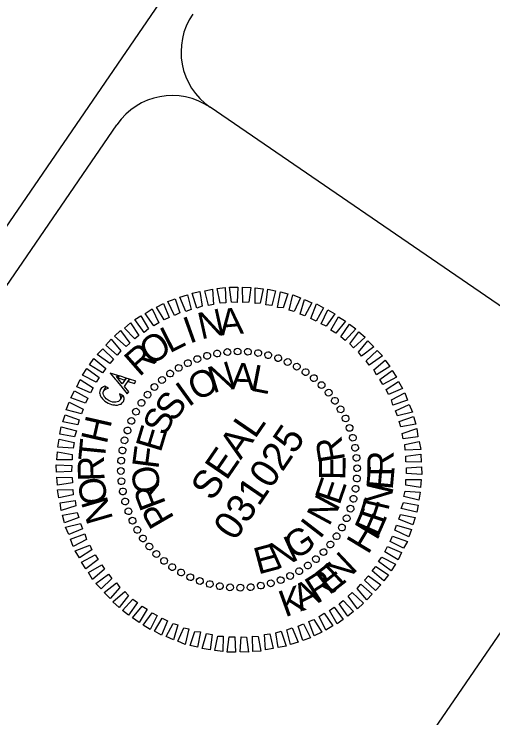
# Model space of a CAD drawing. Extents: x 2312641 to 2338852, y 590461 to 618614.
# Drawn here: x 2334572 to 2335572, y 607939 to 609408 of the extents above; entities that cross this region are included whole.
import ezdxf

# ---------------------------------------------------------------- set-up
doc = ezdxf.new("R2010")
doc.units = 0
doc.layers.add('Default', color=7, linetype='Continuous')
doc.layers.add('Exist Property Iron Pin Cogo Number', color=7, linetype='Continuous')

msp = doc.modelspace()

# ---------------------------------------------------------------- linework, layer by layer
at = {"layer": 'Default'}
for p, q in [((2335018.2, 608703.1), (2335018.2, 608703.1)), ((2335018.2, 608703.1), (2335018.2, 608703.1)), ((2335038.9, 608704.2), (2335038.9, 608704.2)), ((2335038.9, 608704.2), (2335038.9, 608704.2)), ((2335060.7, 608703.3), (2335060.7, 608703.3)), ((2335060.7, 608703.3), (2335060.7, 608703.3)), ((2334954.6, 608687.9), (2334954.6, 608687.9)), ((2334954.6, 608687.9), (2334954.6, 608687.9)), ((2334975.4, 608695.4), (2334975.4, 608695.4)), ((2334975.4, 608695.4), (2334975.4, 608695.4)), ((2334996.1, 608700), (2334996.1, 608700)), ((2334996.1, 608700), (2334996.1, 608700)), ((2335081.9, 608700.6), (2335081.9, 608700.6)), ((2335081.9, 608700.6), (2335081.9, 608700.6)), ((2335102.6, 608696.4), (2335102.6, 608696.4)), ((2335102.6, 608696.4), (2335102.6, 608696.4)), ((2335123.4, 608690.4), (2335123.4, 608690.4)), ((2335123.4, 608690.4), (2335123.4, 608690.4)), ((2334934.9, 608680.2), (2334934.9, 608680.2)), ((2334934.9, 608680.2), (2334934.9, 608680.2)), ((2335143.6, 608681.8), (2335143.6, 608681.8)), ((2335143.6, 608681.8), (2335143.6, 608681.8)), ((2334915.8, 608669.2), (2334915.8, 608669.2)), ((2334915.8, 608669.2), (2334915.8, 608669.2)), ((2335162.9, 608672.6), (2335162.9, 608672.6)), ((2335162.9, 608672.6), (2335162.9, 608672.6)), ((2335181.2, 608661.1), (2335181.2, 608661.1)), ((2335181.2, 608661.1), (2335181.2, 608661.1)), ((2334880.8, 608644.6), (2334880.8, 608644.6)), ((2334880.8, 608644.6), (2334880.8, 608644.6)), ((2334897.9, 608658.1), (2334897.9, 608658.1)), ((2334897.9, 608658.1), (2334897.9, 608658.1)), ((2335198.5, 608648), (2335198.5, 608648)), ((2335198.5, 608648), (2335198.5, 608648)), ((2334865.5, 608629.4), (2334865.5, 608629.4)), ((2334865.5, 608629.4), (2334865.5, 608629.4)), ((2335214.3, 608633.5), (2335214.3, 608633.5)), ((2335214.3, 608633.5), (2335214.3, 608633.5)), ((2335229.1, 608618.5), (2335229.1, 608618.5)), ((2335229.1, 608618.5), (2335229.1, 608618.5)), ((2334851, 608613.6), (2334851, 608613.6)), ((2334851, 608613.6), (2334851, 608613.6)), ((2335242.6, 608601.4), (2335242.6, 608601.4)), ((2335242.6, 608601.4), (2335242.6, 608601.4)), ((2334837.9, 608596.3), (2334837.9, 608596.3)), ((2334837.9, 608596.3), (2334837.9, 608596.3)), ((2334826.4, 608578), (2334826.4, 608578)), ((2334826.4, 608578), (2334826.4, 608578)), ((2335254.1, 608583.2), (2335254.1, 608583.2)), ((2335254.1, 608583.2), (2335254.1, 608583.2)), ((2334817.2, 608558.7), (2334817.2, 608558.7)), ((2334817.2, 608558.7), (2334817.2, 608558.7)), ((2335264.7, 608564.4), (2335264.7, 608564.4)), ((2335264.7, 608564.4), (2335264.7, 608564.4)), ((2335272.8, 608544.4), (2335272.8, 608544.4)), ((2335272.8, 608544.4), (2335272.8, 608544.4)), ((2334808.9, 608538.9), (2334808.9, 608538.9)), ((2334808.9, 608538.9), (2334808.9, 608538.9)), ((2334802.5, 608518.4), (2334802.5, 608518.4)), ((2334802.5, 608518.4), (2334802.5, 608518.4)), ((2335280.3, 608523.6), (2335280.3, 608523.6)), ((2335280.3, 608523.6), (2335280.3, 608523.6)), ((2334798, 608497.2), (2334798, 608497.2)), ((2334798, 608497.2), (2334798, 608497.2)), ((2335284.5, 608503.2), (2335284.5, 608503.2)), ((2335284.5, 608503.2), (2335284.5, 608503.2)), ((2334795.9, 608476.2), (2334795.9, 608476.2)), ((2334795.9, 608476.2), (2334795.9, 608476.2)), ((2335287.6, 608481.1), (2335287.6, 608481.1)), ((2335287.6, 608481.1), (2335287.6, 608481.1)), ((2334794.8, 608454), (2334794.8, 608454)), ((2334794.8, 608454), (2334794.8, 608454)), ((2335041.9, 608457.4), (2335041.9, 608457.4)), ((2335041.9, 608457.4), (2335041.9, 608457.4)), ((2335288.7, 608460.4), (2335288.7, 608460.4)), ((2335288.7, 608460.4), (2335288.7, 608460.4)), ((2335287.9, 608438.6), (2335287.9, 608438.6)), ((2335287.9, 608438.6), (2335287.9, 608438.6)), ((2334795.9, 608433.3), (2334795.9, 608433.3)), ((2334795.9, 608433.3), (2334795.9, 608433.3)), ((2334799.3, 608411.6), (2334799.3, 608411.6)), ((2334799.3, 608411.6), (2334799.3, 608411.6)), ((2335285.5, 608417.1), (2335285.5, 608417.1)), ((2335285.5, 608417.1), (2335285.5, 608417.1)), ((2335281, 608396), (2335281, 608396)), ((2335281, 608396), (2335281, 608396)), ((2334803.9, 608390.9), (2334803.9, 608390.9)), ((2334803.9, 608390.9), (2334803.9, 608390.9)), ((2334810.7, 608369.9), (2334810.7, 608369.9)), ((2334810.7, 608369.9), (2334810.7, 608369.9)), ((2335274.9, 608375.9), (2335274.9, 608375.9)), ((2335274.9, 608375.9), (2335274.9, 608375.9)), ((2334818.8, 608350), (2334818.8, 608350)), ((2334818.8, 608350), (2334818.8, 608350)), ((2335266.3, 608355.7), (2335266.3, 608355.7)), ((2335266.3, 608355.7), (2335266.3, 608355.7)), ((2335257.1, 608336.4), (2335257.1, 608336.4)), ((2335257.1, 608336.4), (2335257.1, 608336.4)), ((2334829.4, 608331.2), (2334829.4, 608331.2)), ((2334829.4, 608331.2), (2334829.4, 608331.2)), ((2334841, 608313), (2334841, 608313)), ((2334841, 608313), (2334841, 608313)), ((2335245.6, 608318.1), (2335245.6, 608318.1)), ((2335245.6, 608318.1), (2335245.6, 608318.1)), ((2334854.4, 608295.9), (2334854.4, 608295.9)), ((2334854.4, 608295.9), (2334854.4, 608295.9)), ((2335232.5, 608300.8), (2335232.5, 608300.8)), ((2335232.5, 608300.8), (2335232.5, 608300.8)), ((2334869.3, 608280.8), (2334869.3, 608280.8)), ((2334869.3, 608280.8), (2334869.3, 608280.8)), ((2335218, 608285), (2335218, 608285)), ((2335218, 608285), (2335218, 608285)), ((2334885.7, 608266.5), (2334885.7, 608266.5)), ((2334885.7, 608266.5), (2334885.7, 608266.5)), ((2335203, 608270.2), (2335203, 608270.2)), ((2335203, 608270.2), (2335203, 608270.2)), ((2334903, 608253.4), (2334903, 608253.4)), ((2334903, 608253.4), (2334903, 608253.4)), ((2335186, 608256), (2335186, 608256)), ((2335186, 608256), (2335186, 608256)), ((2334921.3, 608241.9), (2334921.3, 608241.9)), ((2334921.3, 608241.9), (2334921.3, 608241.9)), ((2334940.2, 608233), (2334940.2, 608233)), ((2334940.2, 608233), (2334940.2, 608233)), ((2335148.9, 608234.6), (2335148.9, 608234.6)), ((2335148.9, 608234.6), (2335148.9, 608234.6)), ((2335168.1, 608244.9), (2335168.1, 608244.9)), ((2335168.1, 608244.9), (2335168.1, 608244.9)), ((2334960.4, 608224.4), (2334960.4, 608224.4)), ((2334960.4, 608224.4), (2334960.4, 608224.4)), ((2334980.9, 608218), (2334980.9, 608218)), ((2334980.9, 608218), (2334980.9, 608218)), ((2335108.1, 608219), (2335108.1, 608219)), ((2335108.1, 608219), (2335108.1, 608219)), ((2335128.9, 608226.5), (2335128.9, 608226.5)), ((2335128.9, 608226.5), (2335128.9, 608226.5)), ((2335002, 608213.5), (2335002, 608213.5)), ((2335002, 608213.5), (2335002, 608213.5)), ((2335023.1, 608211.4), (2335023.1, 608211.4)), ((2335023.1, 608211.4), (2335023.1, 608211.4)), ((2335044.9, 608210.6), (2335044.9, 608210.6)), ((2335044.9, 608210.6), (2335044.9, 608210.6)), ((2335066, 608211.4), (2335066, 608211.4)), ((2335066, 608211.4), (2335066, 608211.4)), ((2335087.7, 608214.8), (2335087.7, 608214.8)), ((2335087.7, 608214.8), (2335087.7, 608214.8))]:
    msp.add_line(p, q, dxfattribs=at)
for points in [[(2335002.2, 608804.9), (2334996.5, 608835.6), (2335012.9, 608837.2), (2335014.2, 608805.2)], [(2335026.3, 608806.7), (2335022.3, 608838.1), (2335039.3, 608838.1), (2335037.7, 608806.2)], [(2335050.1, 608806.3), (2335048.9, 608838.3), (2335066.7, 608837.7), (2335062.1, 608806.6)], [(2335075.4, 608804.4), (2335075.7, 608837.1), (2335092.3, 608834.5), (2335086.3, 608804.8)], [(2334930.8, 608787.7), (2334918.3, 608817), (2334934.3, 608822.5), (2334941.7, 608791.7)], [(2334953.9, 608794.2), (2334944, 608825.5), (2334959.9, 608829.2), (2334965.1, 608798.6)], [(2334978.1, 608799.6), (2334970.6, 608830.3), (2334986.6, 608834), (2334988.5, 608802.1)], [(2335098, 608801.2), (2335102.3, 608833.7), (2335118.3, 608830.3), (2335110, 608799.8)], [(2335122.2, 608795.9), (2335128.3, 608828.4), (2335144, 608824.5), (2335133.8, 608794.8)], [(2335146.5, 608789.9), (2335154.4, 608822.4), (2335169.9, 608815.7), (2335157, 608787.1)], [(2334907.4, 608778.9), (2334893.2, 608808.3), (2334908.7, 608814), (2334918, 608784.3)], [(2335169.4, 608781.9), (2335178.4, 608812.5), (2335194, 608805.8), (2335179.4, 608778.3)], [(2334864.3, 608757.3), (2334846.2, 608783.3), (2334860.5, 608792.7), (2334874.4, 608763.6)], [(2334885.5, 608769.8), (2334869.7, 608796.7), (2334884.5, 608804), (2334895.8, 608774.8)], [(2335191.6, 608772.6), (2335203.4, 608803.1), (2335218.2, 608795.1), (2335203, 608767.5)], [(2335213.1, 608761.4), (2335227.2, 608791), (2335241.7, 608782.6), (2335223.4, 608756.5)], [(2334843.7, 608743.8), (2334824.3, 608770.7), (2334837.2, 608778.6), (2334852.8, 608751.3)], [(2335233.5, 608748.6), (2335249.8, 608776.1), (2335263.8, 608766.9), (2335243.6, 608742.5)], [(2334824.4, 608730.6), (2334803.1, 608752.8), (2334815.4, 608763.5), (2334832.9, 608737.3)], [(2335254.4, 608734.8), (2335272.4, 608761.2), (2335285.4, 608751.5), (2335263.5, 608727.1)], [(2334806.1, 608714.4), (2334782.1, 608736), (2334794.6, 608747.8), (2334814.2, 608721.4)], [(2335272.8, 608719.8), (2335292.2, 608744.7), (2335305, 608733.9), (2335280.9, 608711.5)], [(2334787.5, 608696), (2334763.9, 608717.4), (2334774.9, 608729.6), (2334795.2, 608705)], [(2335290.9, 608702.6), (2335310.9, 608725.9), (2335323, 608713.8), (2335297.6, 608694)], [(2334771.9, 608678.6), (2334745.6, 608697.6), (2334757.7, 608709.7), (2334779.6, 608687.6)], [(2335307.1, 608684.3), (2335329.9, 608706.3), (2335341.1, 608694.8), (2335313.8, 608675.7)], [(2334756.8, 608659.1), (2334729.8, 608676.3), (2334739.1, 608689.6), (2334763.7, 608668.7)], [(2335323, 608665.5), (2335347.2, 608686.1), (2335356.4, 608672.4), (2335328.7, 608655.4)], [(2334743.4, 608639.7), (2334715.1, 608654.8), (2334724.4, 608668.1), (2334750.3, 608649.3)], [(2334799.8, 608626.2), (2334808.6, 608615.3), (2334811.8, 608620), (2334802.9, 608630.7), (2334813.4, 608646.1), (2334806.4, 608648.3), (2334798.2, 608636.4), (2334790.4, 608645.8), (2334790.4, 608645.8), (2334788.3, 608648.1), (2334788.2, 608648.1), (2334786.2, 608650.1), (2334788.8, 608654), (2334773.1, 608659), (2334783.5, 608646.2), (2334785.4, 608643.9), (2334785.4, 608643.8), (2334787.4, 608641.5), (2334787.4, 608641.4), (2334795.2, 608631.9)], [(2335335.7, 608645.4), (2335361.6, 608664.3), (2335370.6, 608650.1), (2335341.8, 608635)], [(2334731.9, 608617.8), (2334703.1, 608630.3), (2334710, 608645.2), (2334737.6, 608628.2)], [(2334786.2, 608650.1), (2334788.8, 608649), (2334791.6, 608653.1), (2334788.8, 608654)], [(2334791.8, 608647.9), (2334803.4, 608644), (2334806.4, 608648.3), (2334794.7, 608652.1), (2334794.6, 608652.1), (2334791.7, 608653), (2334791.6, 608653.1), (2334788.8, 608649), (2334788.9, 608649), (2334791.7, 608647.9)], [(2334810.3, 608641.6), (2334823.5, 608637.1), (2334826.7, 608641.8), (2334813.4, 608646.1)], [(2334798.3, 608596.8), (2334800.7, 608599.5), (2334802.2, 608604.4), (2334802, 608606.2), (2334801.8, 608608.7), (2334801.1, 608610.9), (2334798.6, 608612.2), (2334798.5, 608612.2), (2334793.6, 608602.7), (2334791, 608599.9), (2334790.5, 608599.5), (2334787.3, 608598.5), (2334785.1, 608597.8), (2334781.2, 608598.1), (2334778, 608598.4), (2334771, 608601.1), (2334771, 608601.1), (2334764.6, 608605.4), (2334762.5, 608607.8), (2334760.5, 608610.1), (2334760.1, 608610.5), (2334759, 608613.7), (2334758.2, 608616), (2334758.5, 608617.5), (2334759.1, 608620.8), (2334764, 608630.2), (2334763.9, 608630.2), (2334761.8, 608631.3), (2334758.9, 608630.3), (2334756.8, 608629), (2334755.1, 608628), (2334751.9, 608623.7), (2334751.4, 608620.7), (2334750.8, 608617.4), (2334751.4, 608615.6), (2334752.3, 608612.8), (2334753.4, 608609.5), (2334753.4, 608609.5), (2334754, 608608.8), (2334754.3, 608608.4), (2334755.6, 608606.9), (2334757.2, 608604.9), (2334757.6, 608604.5), (2334759.6, 608602.1), (2334762.1, 608600.4), (2334768.5, 608596.1), (2334768.5, 608596.1), (2334775.5, 608593.5), (2334778.4, 608592.5), (2334782.3, 608592.2), (2334784.1, 608592), (2334786.6, 608591.8), (2334786.8, 608591.8), (2334788, 608591.7), (2334788.1, 608591.7), (2334791.9, 608593), (2334794.1, 608593.7), (2334795.9, 608594.2)], [(2334768.5, 608627), (2334769.3, 608627.2), (2334768.8, 608627.5), (2334766.7, 608628.6), (2334765.1, 608629.5), (2334765.1, 608629.5), (2334764.8, 608629.7), (2334764, 608630.2), (2334759.1, 608620.8), (2334761.9, 608624.2), (2334762.6, 608624.6), (2334765.4, 608626.2)], [(2335349.2, 608624.8), (2335374.6, 608641), (2335383.3, 608626.5), (2335353.5, 608614.3)], [(2334721.2, 608596), (2334690.8, 608607.2), (2334698.5, 608621.5), (2334726.4, 608606.7)], [(2334794.8, 608607.3), (2334793.6, 608602.7), (2334798.5, 608612.2), (2334797.5, 608612.7), (2334797.3, 608612.8), (2334795.2, 608613.9), (2334793.8, 608614.6), (2334792.7, 608615.2), (2334792.7, 608615.2), (2334793.3, 608613.7), (2334794.1, 608611.6), (2334794.7, 608607.6)], [(2335360.4, 608603.3), (2335388.2, 608617.9), (2335393.7, 608602), (2335363.2, 608591.5)], [(2334713.4, 608573.5), (2334681.4, 608582.2), (2334687.7, 608598), (2334716.3, 608583.3)], [(2335368.7, 608580.2), (2335397.2, 608593.2), (2335403.7, 608577.1), (2335372.7, 608569.3)], [(2334705.3, 608550.5), (2334674.2, 608556.9), (2334679.3, 608571.8), (2334708.1, 608561.1)], [(2335376.2, 608557.6), (2335406.2, 608568.4), (2335410.7, 608551.9), (2335379.5, 608546.6)], [(2334698.4, 608525.7), (2334667.8, 608531.1), (2334671, 608546.7), (2334702.9, 608538)], [(2335382.3, 608532.9), (2335412.9, 608542.8), (2335415.4, 608525.9), (2335384.3, 608521.7)], [(2334695.4, 608502.3), (2334663.8, 608504.3), (2334666.4, 608520.8), (2334698.1, 608513.6)], [(2335387.8, 608510), (2335417.7, 608516.1), (2335421.3, 608499.1), (2335388.8, 608498.1)], [(2334693.4, 608477.8), (2334661.5, 608477.6), (2334663.3, 608494.7), (2334693.6, 608488.8)], [(2335389.7, 608485.1), (2335421, 608489.8), (2335422.1, 608472.6), (2335390.3, 608473.5)], [(2334692, 608453.4), (2334661.1, 608451.9), (2334660.4, 608467.1), (2334693.1, 608465.7)], [(2335391.5, 608461), (2335422.7, 608462.8), (2335423.5, 608447), (2335391.2, 608448.9)], [(2334694.1, 608429.7), (2334662.7, 608425), (2334661.8, 608441.5), (2334693.9, 608441)], [(2335390.1, 608436.6), (2335422, 608436.8), (2335420.5, 608420.1), (2335390.1, 608424.9)], [(2334696, 608404.9), (2334666, 608398.7), (2334662.7, 608415), (2334695.1, 608416)], [(2335388.4, 608412.4), (2335420, 608410.5), (2335417.1, 608393.5), (2335386.1, 608401)], [(2334701.5, 608381.8), (2334670.8, 608372), (2334668.6, 608388.2), (2334699.6, 608392.5)], [(2335385.1, 608388.7), (2335415.7, 608383.3), (2335412.8, 608368.2), (2335380.5, 608376.4)], [(2334707.6, 608357.2), (2334677.5, 608346.4), (2334673.2, 608362.2), (2334704.4, 608367.5)], [(2335378.6, 608363.6), (2335409.3, 608357.5), (2335404.6, 608342.3), (2335375.6, 608353.7)], [(2334715.2, 608333.9), (2334686.5, 608321.6), (2334679.8, 608337.3), (2334710.8, 608345.1)], [(2335370.8, 608341), (2335402.1, 608332.2), (2335396.1, 608316.8), (2335367.2, 608331.1)], [(2334723.2, 608311.1), (2334696, 608296.6), (2334689.9, 608312.3), (2334720.4, 608322.9)], [(2335362.3, 608318.3), (2335393.4, 608307.4), (2335385.3, 608293.3), (2335357.5, 608307.4)], [(2334734.6, 608290), (2334708.9, 608273.3), (2334700.2, 608287.9), (2334730.5, 608299.8)], [(2335351.6, 608296.6), (2335381.1, 608284.2), (2335374, 608268.9), (2335346.3, 608285.9)], [(2334748.1, 608269.3), (2334721.9, 608250.1), (2334713.3, 608264), (2334741.8, 608279.4)], [(2335340.1, 608274.7), (2335368.4, 608259.6), (2335359.1, 608246.3), (2335333.2, 608265.1)], [(2334760.8, 608249.3), (2334736.3, 608228.2), (2334727.4, 608242.4), (2334755.3, 608258.8)], [(2335327.2, 608255), (2335354.1, 608237.9), (2335344.4, 608224.8), (2335319.8, 608245.7)], [(2334776.4, 608230.1), (2334754.3, 608208.1), (2334743.1, 608219.7), (2334769.7, 608238.7)], [(2335312, 608235.5), (2335337.9, 608216.7), (2335326.5, 608204.8), (2335303.9, 608226.8)], [(2334792.8, 608211.1), (2334772.6, 608188.5), (2334760.5, 608200.6), (2334786.1, 608220.8)], [(2335296, 608218.4), (2335319.9, 608197.4), (2335308.9, 608185.2), (2335288.7, 608209.1)], [(2334811.1, 608194.3), (2334791.4, 608169.7), (2334778.8, 608180.9), (2334803.3, 608203)], [(2335277.7, 608200.4), (2335301.7, 608178.8), (2335289, 608166.5), (2335270, 608193.1)], [(2334829.8, 608179.7), (2334811.4, 608153.5), (2334798.4, 608163.3), (2334820.4, 608187)], [(2335259.4, 608184.2), (2335280.8, 608161.3), (2335268.7, 608151), (2335250.6, 608177.1)], [(2334850, 608165.8), (2334833.7, 608138.3), (2334819.7, 608147.5), (2334839.9, 608171.9)], [(2335240.3, 608170.3), (2335259.5, 608144.1), (2335246.7, 608135.5), (2335230.8, 608163.1)], [(2334870.8, 608152.7), (2334856.3, 608123.4), (2334842, 608132.2), (2334860.4, 608158.4)], [(2334892.3, 608141.5), (2334880.4, 608111.7), (2334865.6, 608119.7), (2334881.2, 608147)], [(2335198, 608144.6), (2335214.5, 608117.8), (2335199, 608110.4), (2335187.9, 608140)], [(2335219.9, 608157.3), (2335237.4, 608131.1), (2335223.2, 608122.1), (2335209.2, 608150.8)], [(2334914.3, 608132.9), (2334905.1, 608101.9), (2334889.5, 608108.6), (2334904.5, 608135.9)], [(2335176.1, 608135.4), (2335190.7, 608105.8), (2335174.8, 608100.4), (2335165.5, 608130.1)], [(2334937.3, 608124.9), (2334929.2, 608092), (2334914.3, 608098.8), (2334926.5, 608127.3)], [(2334961.3, 608118.5), (2334955.5, 608086.4), (2334939.8, 608090.3), (2334949.7, 608119.6)], [(2334985.5, 608113.2), (2334981.9, 608080.8), (2334965.2, 608084.1), (2334973.8, 608115)], [(2335105.9, 608114.6), (2335113.3, 608083.8), (2335097.2, 608080.8), (2335095.3, 608112.7)], [(2335130, 608119.9), (2335140, 608088.6), (2335123.9, 608085.7), (2335118.7, 608116.2)], [(2335153, 608127.1), (2335165.6, 608097.1), (2335149.5, 608092.3), (2335141.8, 608122.7)], [(2335008.5, 608109.7), (2335007.8, 608077.3), (2334991.3, 608079.9), (2334997.5, 608109.9)], [(2335033.4, 608108.1), (2335034.7, 608076.1), (2335017.2, 608076.4), (2335021.6, 608108.2)], [(2335057.3, 608107.7), (2335061.7, 608076), (2335044.5, 608076.7), (2335046.5, 608108.4)], [(2335081.8, 608109.2), (2335087.4, 608078.5), (2335070.9, 608077.5), (2335069.7, 608109.6)]]:
    msp.add_lwpolyline(points, close=True, dxfattribs=at)
for centre, major_axis in [((2334975.2, 608694.8), (-1.91, 6.82)), ((2334996.2, 608699.7), (-1.31, 6.96)), ((2335017.5, 608702.8), (-0.7, 7.05)), ((2335038.9, 608703.9), (-0.08, 7.08)), ((2335060.4, 608703.3), (0.54, 7.06)), ((2335081.8, 608700.7), (1.15, 6.99)), ((2335102.9, 608696.3), (1.75, 6.86)), ((2334935, 608679.6), (-3.07, 6.38)), ((2334954.8, 608688.1), (-2.5, 6.62)), ((2335123.5, 608690), (2.34, 6.68)), ((2335143.4, 608682), (2.92, 6.45)), ((2334916, 608669.5), (-3.61, 6.09)), ((2335162.6, 608672.3), (3.47, 6.17)), ((2334898, 608657.7), (-4.13, 5.75)), ((2335180.9, 608661), (3.99, 5.85)), ((2334881.1, 608644.4), (-4.61, 5.37)), ((2335198.1, 608648.1), (4.49, 5.48)), ((2334865.4, 608629.7), (-5.06, 4.95)), ((2335214.1, 608633.7), (4.95, 5.06)), ((2334851.1, 608613.7), (-5.48, 4.49)), ((2335228.9, 608618), (5.37, 4.61)), ((2334838.2, 608596.5), (-5.85, 3.99)), ((2335242.1, 608601.1), (5.75, 4.13)), ((2334826.8, 608578.2), (-6.17, 3.47)), ((2335253.9, 608583.1), (6.09, 3.61)), ((2335264.1, 608564.1), (6.38, 3.07)), ((2334817.1, 608559), (-6.45, 2.92)), ((2334809.1, 608539), (-6.68, 2.34)), ((2335272.5, 608544.3), (6.62, 2.5)), ((2334802.9, 608518.4), (-6.86, 1.75)), ((2335279.2, 608523.9), (6.82, 1.91)), ((2334798.4, 608497.4), (-6.99, 1.15)), ((2335284.1, 608503), (6.96, 1.31)), ((2334795.9, 608476), (-7.06, 0.54)), ((2335287.2, 608481.7), (7.05, 0.7)), ((2335288.4, 608460.2), (7.08, 0.08)), ((2334795.2, 608454.5), (-7.08, -0.08)), ((2334796.4, 608433), (-7.05, -0.7)), ((2335287.7, 608438.7), (7.06, -0.54)), ((2335285.1, 608417.3), (6.99, -1.15)), ((2334799.4, 608411.8), (-6.96, -1.31)), ((2334804.3, 608390.8), (-6.82, -1.91)), ((2335280.7, 608396.3), (6.86, -1.75)), ((2335274.5, 608375.7), (6.68, -2.34)), ((2334811, 608370.4), (-6.62, -2.5)), ((2334819.5, 608350.6), (-6.38, -3.07)), ((2335266.5, 608355.7), (6.45, -2.92)), ((2334829.6, 608331.6), (-6.09, -3.61)), ((2335256.7, 608336.5), (6.17, -3.47)), ((2334841.4, 608313.6), (-5.75, -4.13)), ((2335245.4, 608318.2), (5.85, -3.99)), ((2335232.5, 608301), (5.48, -4.49)), ((2334854.7, 608296.7), (-5.37, -4.61)), ((2335218.1, 608285), (5.06, -4.95)), ((2334869.4, 608281), (-4.95, -5.06)), ((2335202.4, 608270.3), (4.61, -5.37)), ((2334885.4, 608266.6), (-4.49, -5.48)), ((2334902.6, 608253.7), (-3.99, -5.85)), ((2335185.5, 608257), (4.13, -5.75)), ((2334920.9, 608242.4), (-3.47, -6.17)), ((2335167.5, 608245.2), (3.61, -6.09)), ((2334940.1, 608232.7), (-2.92, -6.45)), ((2334960.1, 608224.7), (-2.34, -6.68)), ((2335128.8, 608226.6), (2.5, -6.62)), ((2335148.5, 608235.1), (3.07, -6.38)), ((2334980.7, 608218.4), (-1.75, -6.86)), ((2335001.7, 608214), (-1.15, -6.99)), ((2335023.1, 608211.5), (-0.54, -7.06)), ((2335044.6, 608210.8), (0.08, -7.08)), ((2335066.1, 608212), (0.7, -7.05)), ((2335087.4, 608215), (1.31, -6.96)), ((2335108.3, 608219.9), (1.91, -6.82))]:
    msp.add_ellipse(centre, major_axis=major_axis, ratio=0.999708, dxfattribs=at)
at = {"layer": 'Exist Property Iron Pin Cogo Number'}
for p, q in [((2324877.7, 594842), (2336116.1, 611240.6)), ((2336829.3, 607947.5), (2334981.6, 609213.7)), ((2333205.9, 606870.4), (2334787, 609177.4)), ((2334158.7, 606032.4), (2335905.2, 608580.8))]:
    msp.add_line(p, q, dxfattribs=at)
for centre, start, end in [((2335060.8, 609329.2), 145.5761, 235.5761), ((2334902.5, 609098.3), 55.5761, 145.5761)]:
    msp.add_arc(centre, 140, start, end, dxfattribs=at)

# ---------------------------------------------------------------- texts
at = {"layer": 'Default'}
for s, height, rotation, p in [('N', 55.4, 12.4759, (2334962.8, 608728.9)), ('A', 55.4, 5.2742, (2335003.4, 608737)), ('A', 55.4, 5.2742, (2335003.4, 608737)), ('I', 55.4, 19.6772, (2334938.4, 608719.7)), ('L', 55.4, 26.8779, (2334896.8, 608699.4)), ('O', 55.4, 34.0782, (2334857.9, 608673.2)), ('R', 55.4, 41.2781, (2334833.6, 608649.8)), ('N', 55.4, 17.1336, (2334987.5, 608616.2)), ('A', 55.4, 358.4173, (2335024.4, 608624.9)), ('L', 55.5, 349.0579, (2335063.5, 608622.7)), ('O', 55.4, 26.4905, (2334952.9, 608599.5)), ('I', 55.4, 35.8466, (2334936.4, 608586.8)), ('S', 55.4, 54.5574, (2334907.1, 608554.9)), ('S', 55.4, 63.9126, (2334888.1, 608525.1)), ('H', 55.4, 77.2765, (2334765.7, 608509)), ('SEAL', 58.98, 55.657, (2334986, 608389.4)), ('E', 55.4, 73.2681, (2334878.3, 608491.4)), ('031025', 59, 55.657, (2335033.4, 608306.2)), ('R', 55.4, 99.1384, (2335263.6, 608476.9)), ('T', 55.4, 84.4768, (2334761.4, 608473)), ('F', 55.4, 82.6241, (2334873.4, 608457)), ('R', 55.4, 91.6775, (2334761.4, 608433.6)), ('R', 55.4, 90.0667, (2335365, 608443.4)), ('E', 55.4, 89.7811, (2335264, 608435.4)), ('O', 55.4, 101.3383, (2334880.2, 608413.7)), ('E', 55.4, 84.7862, (2335362.4, 608413.7)), ('O', 55.4, 98.8788, (2334768.2, 608388.5)), ('E', 55.4, 71.0688, (2335251.4, 608381.3)), ('R', 55.4, 110.6967, (2334890.1, 608386)), ('N', 55.4, 76.8194, (2335353.2, 608369.7)), ('N', 55.4, 106.0805, (2334779.6, 608353.9)), ('N', 55.4, 61.7134, (2335229.6, 608337.4)), ('F', 55.4, 71.6077, (2335344, 608341.8)), ('P', 55.5, 120.0559, (2334908, 608355.9)), ('E', 55.4, 66.3272, (2335332.1, 608314.5)), ('I', 55.4, 52.3582, (2335210.6, 608310.5)), ('G', 55.4, 33.6473, (2335159.2, 608267.2)), ('H', 55.4, 58.9114, (2335311.2, 608278.3)), ('N', 55.4, 24.291, (2335120.2, 608248.1)), ('E', 55.4, 14.9339, (2335081.8, 608238.1)), ('N', 55.4, 43.3682, (2335253.3, 608212.7)), ('E', 55.4, 38.0877, (2335229.9, 608194.2)), ('R', 55.4, 32.5316, (2335203.5, 608177.3)), ('A', 55.4, 25.9654, (2335170.4, 608160.6)), ('K', 55.4, 19.8124, (2335137.9, 608148.6))]:
    msp.add_text(s, height=height, rotation=rotation, dxfattribs=at).set_placement(p)

doc.saveas('drawing.dxf')
